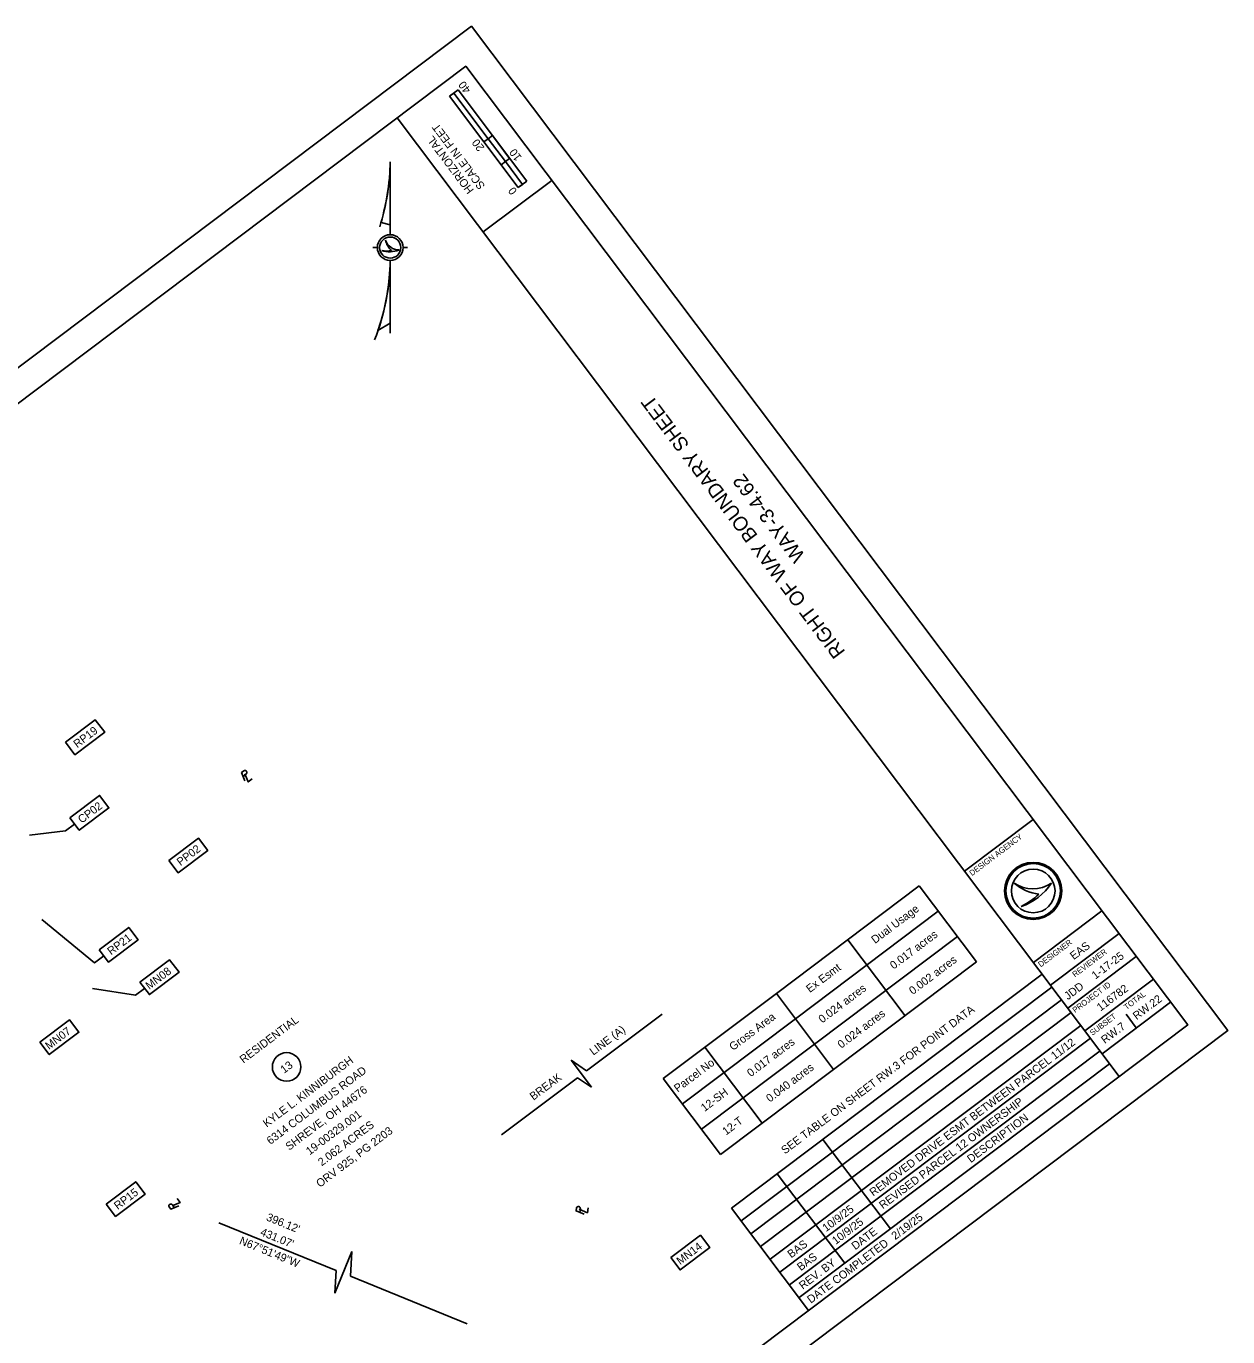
# Model space of a CAD drawing. Extents: x 120163 to 120971, y 463167 to 463927.
# Drawn here: x 120550.8 to 120971.3, y 463468.7 to 463927.3 of the extents above; entities that cross this region are included whole.
import ezdxf

# ---------------------------------------------------------------- set-up
doc = ezdxf.new("R2010")
doc.units = 0
for name, color, linetype in [('GE_X_Alignment', 7, 'Continuous'), ('RD_X_Cells', 7, 'Continuous'), ('RD_X_RR_Cells', 7, 'Continuous'), ('SV_P_Mon_Cells_Set', 7, 'Continuous'), ('SV_X_Mon_Cells_Found', 7, 'Continuous')]:
    doc.layers.add(name, color=color, linetype=linetype)

msp = doc.modelspace()

# ---------------------------------------------------------------- linework, layer by layer
at = {"layer": 'GE_X_Alignment'}
for p, q in [((120626.7, 463664.8), (120627.74, 463665.58)), ((120627.72, 463664.78), (120627.72, 463664.78)), ((120602.73, 463513.84), (120601.95, 463514.87)), ((120602.75, 463514.85), (120602.75, 463514.85)), ((120744.53, 463512.18), (120744.71, 463513.46)), ((120745.26, 463512.88), (120745.26, 463512.88))]:
    msp.add_line(p, q, dxfattribs=at)
for points in [[(120627.32, 463663.27), (120626.16, 463666.11), (120626.99, 463666.73)], [(120627.35, 463665.71), (120628.5, 463662.87), (120629.89, 463663.92)], [(120604.26, 463514.46), (120601.42, 463513.3), (120600.8, 463514.13)], [(120601.82, 463514.49), (120604.66, 463515.63), (120603.61, 463517.03)], [(120746.05, 463511.54), (120743.22, 463512.73), (120743.37, 463513.75)], [(120744.35, 463513.28), (120747.16, 463512.08), (120747.41, 463513.81)]]:
    msp.add_lwpolyline(points, dxfattribs=at)
for centre, start, end in [((120627.32, 463666.12), 307.4541, 118.3112), ((120601.41, 463514.45), 37.4541, 208.3112), ((120744.03, 463513.55), 352.4541, 163.3112)]:
    msp.add_arc(centre, 0.69, start, end, dxfattribs=at)
at = {"layer": 'RD_X_Cells'}
msp.add_lwpolyline([(120428.08, 463166.76), (120971.27, 463575.83), (120706.58, 463927.31), (120163.39, 463518.23)], close=True, dxfattribs=at)
at = {"layer": 'RD_X_RR_Cells'}
for p, q in [((120701.93, 463905.03), (120698.93, 463902.77)), ((120698.93, 463902.77), (120700.43, 463903.9)), ((120700.43, 463903.9), (120700.44, 463903.91)), ((120700.44, 463903.91), (120712.47, 463887.93)), ((120701.93, 463905.03), (120725.99, 463873.08)), ((120723, 463870.82), (120698.93, 463902.77)), ((120710.97, 463886.8), (120698.93, 463902.77)), ((120712.47, 463887.93), (120710.97, 463886.8)), ((120713.95, 463889.04), (120712.46, 463887.92)), ((120712.46, 463887.92), (120718.47, 463879.93)), ((120719.96, 463881.05), (120713.95, 463889.04)), ((120718.47, 463879.93), (120719.96, 463881.05)), ((120678.18, 463854.34), (120678.18, 463879.84)), ((120718.47, 463879.93), (120716.98, 463878.81)), ((120716.98, 463878.81), (120723, 463870.82)), ((120724.49, 463871.94), (120718.47, 463879.93)), ((120725.99, 463873.08), (120723, 463870.82)), ((120723, 463870.82), (120724.49, 463871.94)), ((120674.99, 463858.65), (120678.18, 463857.78)), ((120672.08, 463849.84), (120673.68, 463849.84)), ((120682.68, 463849.84), (120684.28, 463849.84)), ((120678.18, 463819.84), (120678.18, 463845.34)), ((120678.18, 463823.34), (120673.89, 463820.77)), ((120896.54, 463627.44), (120896.54, 463627.44)), ((120903.18, 463624.7), (120903.18, 463624.7)), ((120909.55, 463627.45), (120909.55, 463627.45)), ((120898.95, 463619.24), (120898.95, 463619.24)), ((120939.27, 463576.77), (120935.66, 463581.56))]:
    msp.add_line(p, q, dxfattribs=at)
for points in [[(120674.97, 463858.66), (120674.99, 463858.65), (120678.18, 463857.78), (120678.18, 463879.84)], [(120673.89, 463820.77), (120678.18, 463823.34), (120678.18, 463845.34)]]:
    msp.add_lwpolyline(points, dxfattribs=at)
for centre, radius in [((120678.18, 463849.84), 4.5), ((120678.18, 463849.84), 3.7), ((120903.18, 463624.7), 10), ((120903.18, 463624.7), 9.54), ((120903.18, 463624.7), 9.54), ((120903.18, 463624.7), 7.64)]:
    msp.add_circle(centre, radius, dxfattribs=at)
for centre, radius, start, end in [((120599.33, 463880.95), 78.85, 342.4153, 359.1947), ((120599.33, 463880.95), 78.85, 343.5754, 359.1947), ((120677.96, 463857.42), 9.05, 252.4874, 291.486), ((120677.07, 463860.07), 11.43, 260.7277, 277.8734), ((120681.33, 463854.1), 5.1, 199.1575, 269.3709), ((120683.5, 463854.02), 7.17, 192.8556, 227.3141), ((120599.33, 463846.45), 78.85, 338.5054, 359.1947), ((120599.33, 463846.45), 78.85, 340.9936, 359.1947), ((120903.04, 463637.05), 11.6, 235.9151, 304.1489), ((120903.04, 463637.05), 11.6, 235.9088, 235.9151), ((120907.05, 463639.38), 15.91, 228.6211, 228.6253), ((120907.05, 463639.38), 15.91, 228.6253, 263.0778), ((120892.54, 463638.47), 20.26, 288.4408, 327.0664), ((120887.66, 463641.91), 25.32, 296.4827, 313.6504), ((120887.66, 463641.91), 25.32, 296.4795, 296.4827), ((120892.54, 463638.47), 20.26, 288.4359, 288.4408)]:
    msp.add_arc(centre, radius, start, end, dxfattribs=at)
at = {"layer": 'SV_P_Mon_Cells_Set'}
for p, q in [((120813.3, 463588.8), (120863.3, 463626.47)), ((120863.3, 463626.47), (120883.34, 463599.87)), ((120819.97, 463579.94), (120869.98, 463617.6)), ((120826.65, 463571.07), (120876.66, 463608.73)), ((120838.3, 463607.63), (120858.33, 463581.03)), ((120833.33, 463562.2), (120883.34, 463599.87)), ((120797.66, 463513.69), (120906.36, 463595.54)), ((120773.75, 463559.02), (120813.3, 463588.8)), ((120801.03, 463509.21), (120909.72, 463591.07)), ((120813.3, 463588.8), (120833.33, 463562.2)), ((120804.4, 463504.74), (120913.09, 463586.59)), ((120773.35, 463581.62), (120746.89, 463561.75)), ((120780.43, 463550.16), (120819.97, 463579.94)), ((120807.77, 463500.27), (120916.46, 463582.12)), ((120811.14, 463495.79), (120919.83, 463577.65)), ((120814.51, 463491.32), (120923.2, 463573.17)), ((120787.1, 463541.29), (120826.65, 463571.07)), ((120788.29, 463569.97), (120808.32, 463543.37)), ((120817.88, 463486.85), (120926.57, 463568.7)), ((120748.64, 463555.97), (120741.55, 463565.42)), ((120746.89, 463561.75), (120741.55, 463565.42)), ((120821.24, 463482.37), (120929.94, 463564.23)), ((120793.78, 463532.42), (120833.33, 463562.2)), ((120933.31, 463559.75), (120933.31, 463559.75)), ((120743.68, 463559.33), (120717.13, 463539.39)), ((120748.64, 463555.97), (120743.68, 463559.33)), ((120773.75, 463559.02), (120793.78, 463532.42)), ((120829.61, 463537.75), (120853.2, 463506.44)), ((120813.64, 463525.72), (120837.22, 463494.4)), ((120797.66, 463513.69), (120824.61, 463477.9)), ((120659.26, 463491.87), (120618.25, 463508.55)), ((120658.82, 463483.89), (120664.76, 463498.48)), ((120664.23, 463489.85), (120664.76, 463498.48)), ((120658.82, 463483.89), (120659.26, 463491.87)), ((120705.09, 463473.22), (120664.23, 463489.85))]:
    msp.add_line(p, q, dxfattribs=at)
for points in [[(120564.6, 463676.73), (120574.98, 463684.55), (120578.26, 463680.2), (120567.87, 463672.38)], [(120566.1, 463650.28), (120576.49, 463658.11), (120579.77, 463653.76), (120569.38, 463645.93)], [(120600.66, 463635.39), (120611.05, 463643.21), (120614.33, 463638.86), (120603.94, 463631.04)], [(120576.31, 463604.13), (120586.7, 463611.95), (120589.98, 463607.6), (120579.59, 463599.78)], [(120590.61, 463592.75), (120601, 463600.57), (120604.28, 463596.22), (120593.89, 463588.4)], [(120555.56, 463571.78), (120565.95, 463579.6), (120569.23, 463575.25), (120558.84, 463567.43)], [(120578.77, 463515.12), (120589.16, 463522.95), (120592.44, 463518.6), (120582.05, 463510.77)], [(120776.34, 463496.4), (120786.73, 463504.23), (120790.01, 463499.88), (120779.62, 463492.05)]]:
    msp.add_lwpolyline(points, close=True, dxfattribs=at)
for points in [[(120567.74, 463648.11), (120564.55, 463645.7), (120551.99, 463644.19)], [(120577.95, 463601.95), (120574.75, 463599.55), (120556.26, 463614.68)], [(120592.25, 463590.57), (120589.06, 463588.17), (120574.03, 463590.51)]]:
    msp.add_lwpolyline(points, dxfattribs=at)
msp.add_circle((120641.93, 463563.1), 5, dxfattribs=at)
at = {"layer": 'SV_X_Mon_Cells_Found'}
for p, q in [((120933.31, 463559.75), (120680.64, 463895.26)), ((120710.72, 463855.32), (120734.69, 463873.36)), ((120879.16, 463631.65), (120903.13, 463649.7)), ((120903.23, 463599.7), (120927.19, 463617.74)), ((120909.24, 463591.71), (120933.21, 463609.75)), ((120915.26, 463583.72), (120939.22, 463601.77)), ((120921.27, 463575.73), (120945.24, 463593.78)), ((120927.29, 463567.74), (120951.25, 463585.79))]:
    msp.add_line(p, q, dxfattribs=at)
msp.add_lwpolyline([(120193.37, 463528.29), (120704.61, 463913.3), (120957.27, 463577.8), (120446.03, 463192.79)], close=True, dxfattribs=at)

# ---------------------------------------------------------------- texts
at = {"layer": 'RD_X_RR_Cells'}
for s, height, rotation, p in [('40', 2.8, 126.9831, (120706.56, 463905.07)), ('SCALE IN FEET', 2.8, 126.9831, (120711.52, 463871.46)), ('HORIZONTAL', 2.8, 126.9831, (120707.58, 463869.96)), ('20', 2.8, 126.9831, (120711.28, 463884.84)), ('10', 2.8, 126.9831, (120724.36, 463881.43)), ('0', 2.8, 126.9831, (120722.73, 463869.65)), ('RIGHT OF WAY BOUNDARY SHEET', 5, 126.9831, (120837.61, 463708.43)), ('WAY-3-4.62', 5, 126.9831, (120823.59, 463742.01)), ('DESIGN AGENCY', 2, 36.9831, (120881.77, 463629.85)), ('DESIGNER', 2, 36.9831, (120905.83, 463597.9)), ('EAS', 2.8, 36.9831, (120917.36, 463600.45)), ('REVIEWER', 2, 36.9831, (120917.79, 463594.39)), ('1-17-25', 2.8, 36.9831, (120924.93, 463593.63)), ('JDD', 2.8, 36.9831, (120915.34, 463586.41)), ('PROJECT ID', 2, 36.9831, (120917.86, 463581.92)), ('116782', 2.8, 36.9831, (120926.74, 463582.47)), ('TOTAL', 2, 36.9831, (120935.86, 463582.96)), ('RW.22', 2.8, 36.9831, (120939.36, 463579.46)), ('SUBSET', 2, 36.9831, (120923.88, 463573.94)), ('RW.7', 2.8, 36.9831, (120928.25, 463571.1))]:
    msp.add_text(s, height=height, rotation=rotation, dxfattribs=at).set_placement(p)
at = {"layer": 'SV_P_Mon_Cells_Set'}
for s, height, rotation, p in [('RP19', 2.8, 36.9831, (120568.64, 463674.62)), ('CP02', 2.8, 36.9831, (120570.22, 463648.22)), ('PP02', 2.8, 36.9831, (120604.79, 463633.34)), ('Dual Usage', 2.808, 36.9831, (120847.83, 463606.11)), ('0.017 acres', 2.8083, 36.9831, (120854.36, 463597.13)), ('RP21', 2.8, 36.9831, (120580.49, 463602.12)), ('0.002 acres', 2.8083, 36.9831, (120861.04, 463588.26)), ('MN08', 2.8, 36.9831, (120593.87, 463590.04)), ('Ex Esmt', 2.808, 36.9831, (120825.02, 463588.93)), ('0.024 acres', 2.8083, 36.9831, (120829.36, 463578.3)), ('SEE TABLE ON SHEET RW.3 FOR POINT DATA', 2.8, 36.9831, (120816.31, 463532.46)), ('0.024 acres', 2.8083, 36.9831, (120836.03, 463569.43)), ('RESIDENTIAL', 2.8, 36.9831, (120626.81, 463564.23)), ('Gross Area', 2.808, 36.9831, (120798.11, 463568.66)), ('MN07', 2.8, 36.9831, (120558.76, 463569.02)), ('BREAK             LINE (A)', 2.8, 36.9206, (120728.3, 463551.27)), ('0.017 acres', 2.8083, 36.9831, (120804.35, 463559.47)), ('REMOVED DRIVE ESMT BETWEEN PARCEL 11/12  ', 2.8, 36.9831, (120847.21, 463517.7)), ('KYLE L. KINNIBURGH', 2.8, 36.9831, (120634.97, 463541.83)), ('13', 2.8, 36.9831, (120641.05, 463560.68)), ('Parcel No.', 2.808, 36.9831, (120778.78, 463554.11)), ('6314 COLUMBUS ROAD', 2.8, 36.9831, (120636.25, 463535.78)), ('0.040 acres', 2.8083, 36.9831, (120811.03, 463550.6)), ('SHREVE, OH 44676', 2.8, 36.9831, (120642.84, 463533.74)), ('12-SH', 2.808, 36.9831, (120788.19, 463547.3)), ('REVISED PARCEL 12 OWNERSHIP            ', 2.8, 36.9831, (120850.58, 463513.23)), ('19-00329.001', 2.8, 36.9831, (120649.99, 463532.11)), ('12-T', 2.808, 36.9831, (120795.7, 463539.05)), ('DESCRIPTION', 2.8, 36.9831, (120881.36, 463529.4)), ('ORV 925, PG 2203', 2.8, 36.9831, (120653.57, 463520.79)), ('2.062 ACRES', 2.8, 36.9831, (120654.2, 463528.27)), ('RP15', 2.8, 36.9831, (120582.83, 463513.02)), (' 10/9/25', 2.8, 36.9831, (120829.89, 463504.65)), ("396.12'", 2.8, 337.8637, (120634.58, 463509.49)), (' 10/9/25', 2.8, 36.9831, (120833.25, 463500.18)), ('2/19/25                             ', 2.8, 36.9831, (120854.89, 463502.45)), ("431.07'", 2.8, 337.8637, (120632.47, 463504.3)), ('DATE', 2.8, 36.9831, (120840.9, 463498.93)), ('N67°51\'49"W', 2.8, 337.8637, (120625.14, 463501.24)), ('MN14', 2.8, 36.9831, (120779.65, 463493.73)), ('BAS', 2.8, 36.9831, (120818.49, 463496.07)), ('DATE COMPLETED', 2.8, 36.9831, (120825.37, 463480.22)), ('BAS', 2.8, 36.9831, (120821.85, 463491.59)), ('REV. BY', 2.8, 36.9831, (120822.54, 463485.1))]:
    msp.add_text(s, height=height, rotation=rotation, dxfattribs=at).set_placement(p)

doc.saveas('drawing.dxf')
